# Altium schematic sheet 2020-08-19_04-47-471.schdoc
size 232 x 111 mm; SheetNumber: 1; SheetTotal: 1
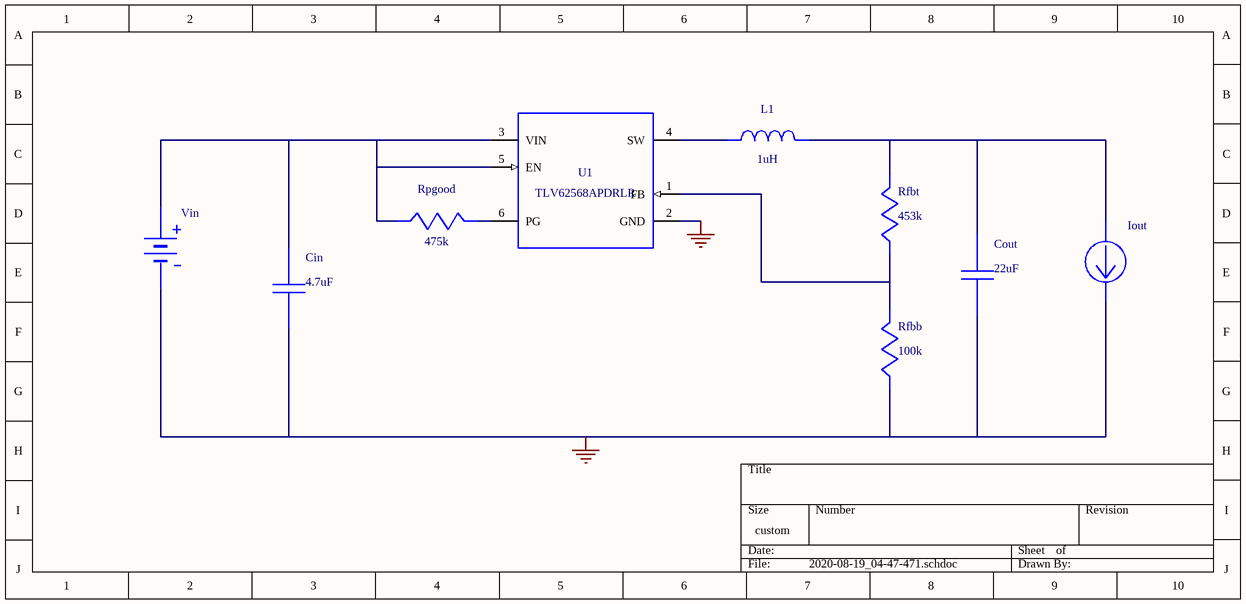
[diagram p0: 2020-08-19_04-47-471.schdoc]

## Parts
Cin  value 4.7uF  (hidden comment: C1608X7S1A475K080AC)
Cout  value 22uF  (hidden comment: GRM188R60J226MEA0D)
Iout  WB_CURRENT_LOAD  (value not drawn)
L1  value 1uH  (hidden comment: IFSC1515AHER1R0M01)
Rfbb  value 100k  (hidden comment: CRCW0402100KFKED)
Rfbt  value 453k  (hidden comment: CRCW0402453KFKED)
Rpgood  value 475k  (hidden comment: CRCW0402475KFKED)
U1  TLV62568APDRLR
Vin  WB_BATTERY  (value not drawn)

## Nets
0: Cin.2 Cout.2 Iout.2(-) Rfbb.2 U1.2(GND) Vin.2(-)
NetCin_1: Cin.1 Rpgood.2 U1.3(VIN) U1.5(EN) Vin.1(+)
NetCout_1: Cout.1 Iout.1(+) L1.2 Rfbt.1
NetL1_1: L1.1 U1.4(SW)
NetRfbb_1: Rfbb.1 Rfbt.2 U1.1(FB)
NetRpgood_1: Rpgood.1 U1.6(PG)

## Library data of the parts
Cin = C1608X7S1A475K080AC: C1608X7S1A475K08; Manufacturer Name: TDK
Cout = GRM188R60J226MEA0D: GRM188R60J226MEA; Manufacturer Name: MuRata
L1 = IFSC1515AHER1R0M01: IFSC1515AHER1R0M; Manufacturer Name: Vishay-Dale
Rfbb = CRCW0402100KFKED: Manufacturer Name: Vishay-Dale
Rfbt = CRCW0402453KFKED: Manufacturer Name: Vishay-Dale
Rpgood = CRCW0402475KFKED: Manufacturer Name: Vishay-Dale
U1 = TLV62568APDRLR: Manufacturer Name: Texas Instruments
